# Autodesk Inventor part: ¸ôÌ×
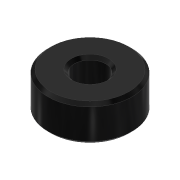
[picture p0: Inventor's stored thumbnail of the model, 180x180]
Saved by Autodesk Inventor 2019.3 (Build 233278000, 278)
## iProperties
Created: 2017-10
Part Number: ¸ôÌ×
Material: Ogólny
Document SubType Name: Modeling
Designer: CADENGINEERING4
Density: 1 g/cm^3
Appearance: Gładki — czarny
Author: CADENGINEERING4
Revision Number: ÈÎºÎ
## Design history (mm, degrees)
feature "Ðý×ª1"
node "Bryła1"
